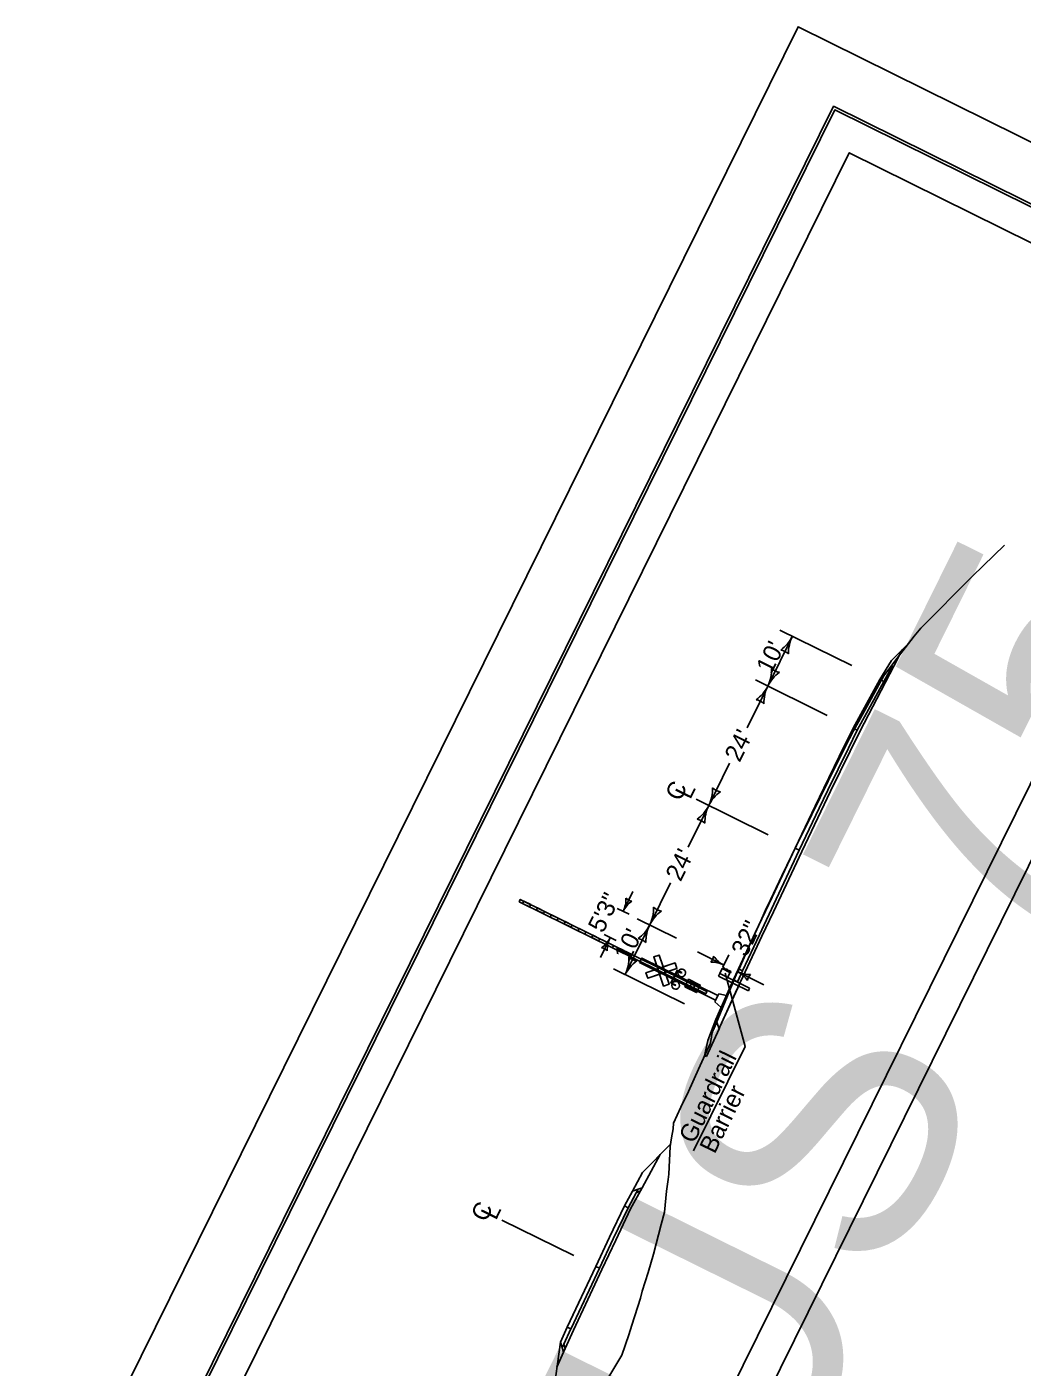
# Model space of a CAD drawing. Extents: x 14090526 to 14125274, y 8637242 to 8677144.
# Drawn here: x 14118796 to 14119513, y 8672010 to 8672975 of the extents above; entities that cross this region are included whole.
import ezdxf

# ---------------------------------------------------------------- set-up
doc = ezdxf.new("R2010")
doc.units = 0
for name, color, linetype in [('dsnCellElements', 7, 'Continuous'), ('dsnNonPlotable', 7, 'Continuous'), ('dsnShadingGranular', 7, 'Continuous'), ('dsnShadingPaved', 7, 'Continuous'), ('dsnStdLineWork', 7, 'Continuous'), ('dsnStgShadingPropPav', 7, 'Continuous'), ('dsnTextOverlapEven', 7, 'Continuous'), ('Level 1', 7, 'Continuous'), ('TC_PCCPavement', 7, 'Continuous'), ('TC_ShoulderEarthFill', 7, 'Continuous'), ('TC_ShoulderGranular', 7, 'Continuous'), ('TC_Subbase', 7, 'Continuous'), ('Terrain', 7, 'Continuous')]:
    doc.layers.add(name, color=color, linetype=linetype)

# ---------------------------------------------------------------- blocks, each defined once
blk = doc.blocks.new('LT')
at = {"layer": 'dsnCellElements'}
for centre, radius, start, end in [((-3.56, 0), 1.64, 342.2666, 17.7333), ((0, 4.25), 4.25, 241.9275, 270), ((0, -4.25), 4.25, 90, 118.0725)]:
    blk.add_arc(centre, radius, start, end, dxfattribs=at)

msp = doc.modelspace()

# ---------------------------------------------------------------- linework, layer by layer
at = {"layer": 'dsnNonPlotable'}
for points in [[(14118795.85, 8671851.12), (14119351.63, 8672975.23), (14120075.94, 8672617.11), (14119520.16, 8671493)], [(14118861.25, 8671870.1), (14119378.04, 8672915.32), (14120012.79, 8672601.49), (14119496.01, 8671556.26)]]:
    msp.add_lwpolyline(points, close=True, dxfattribs=at)
at = {"layer": 'dsnShadingGranular'}
for points in [[(14119294.62, 8672253.43), (14119292.31, 8672260.25), (14119304.91, 8672288.51), (14119307.9, 8672287.03), (14119309.61, 8672286.19), (14119295.27, 8672254.87)], [(14119226.42, 8672126), (14119232.2, 8672136.6), (14119236.39, 8672138.03), (14119234.89, 8672135.27), (14119234.89, 8672135.27), (14119229.11, 8672124.67)], [(14119181.56, 8672023.96), (14119180.29, 8672027.72), (14119185.2, 8672038.75), (14119187.88, 8672037.42), (14119182.75, 8672026.5), (14119182.75, 8672026.5)]]:
    msp.add_lwpolyline(points, close=True, dxfattribs=at)
at = {"layer": 'dsnShadingPaved'}
for points in [[(14119311.6, 8672295.34), (14119323.72, 8672321.14), (14119335.84, 8672346.95), (14119352.39, 8672382.18), (14119359.62, 8672397.31), (14119366.84, 8672412.45), (14119373.09, 8672425.47), (14119387.87, 8672455.61), (14119394.29, 8672468.54), (14119391.3, 8672470.02), (14119384.88, 8672457.08), (14119370.1, 8672426.95), (14119363.86, 8672413.93), (14119356.63, 8672398.79), (14119349.4, 8672383.65), (14119332.85, 8672348.43), (14119320.73, 8672322.61), (14119308.61, 8672296.81)], [(14119185.2, 8672038.75), (14119205.79, 8672082.38), (14119215.78, 8672103.47), (14119226.42, 8672126), (14119229.11, 8672124.67), (14119218.46, 8672102.14), (14119208.48, 8672081.06), (14119188.04, 8672037.74), (14119187.89, 8672037.42)]]:
    msp.add_lwpolyline(points, close=True, dxfattribs=at)
at = {"layer": 'dsnStdLineWork'}
for p, q in [((14119150.63, 8672345.1), (14119151.45, 8672346.76)), ((14119285.08, 8672278.62), (14119150.63, 8672345.1)), ((14119285.91, 8672280.28), (14119151.45, 8672346.76)), ((14119237.36, 8672301.18), (14119239.01, 8672304.5)), ((14119293.79, 8672277.41), (14119239.01, 8672304.5)), ((14119292.14, 8672274.09), (14119237.36, 8672301.18)), ((14119264.45, 8672295.69), (14119259.81, 8672286.31)), ((14119264.66, 8672295.07), (14119260.43, 8672286.52)), ((14119267.89, 8672293.99), (14119264.45, 8672295.69)), ((14119267.69, 8672293.57), (14119264.66, 8672295.07)), ((14119267.69, 8672293.57), (14119267.89, 8672293.99)), ((14119263.26, 8672284.61), (14119259.81, 8672286.31)), ((14119263.46, 8672285.02), (14119260.43, 8672286.52)), ((14119263.26, 8672284.61), (14119263.46, 8672285.02)), ((14119285.08, 8672278.62), (14119285.91, 8672280.28)), ((14119291.53, 8672272.85), (14119294.4, 8672278.66)), ((14119294.4, 8672278.66), (14119300, 8672277.44)), ((14119291.53, 8672272.85), (14119295.89, 8672269.14))]:
    msp.add_line(p, q, dxfattribs=at)
for points in [[(14119150.63, 8672345.1), (14119151.45, 8672346.76), (14119285.91, 8672280.28), (14119285.08, 8672278.62)], [(14119153.12, 8672343.87), (14119153.94, 8672345.53), (14119158.92, 8672343.06), (14119158.1, 8672341.4)], [(14119163.08, 8672338.94), (14119163.9, 8672340.6), (14119168.88, 8672338.14), (14119168.06, 8672336.48)], [(14119173.04, 8672334.02), (14119173.86, 8672335.68), (14119178.84, 8672333.21), (14119178.02, 8672331.55)], [(14119183, 8672329.09), (14119183.82, 8672330.75), (14119188.8, 8672328.29), (14119187.98, 8672326.63)], [(14119192.96, 8672324.17), (14119193.78, 8672325.83), (14119198.76, 8672323.37), (14119197.94, 8672321.71)], [(14119202.92, 8672319.24), (14119203.74, 8672320.9), (14119208.72, 8672318.44), (14119207.9, 8672316.78)], [(14119212.88, 8672314.32), (14119213.7, 8672315.98), (14119218.68, 8672313.52), (14119217.86, 8672311.86)], [(14119222.84, 8672309.39), (14119223.66, 8672311.05), (14119228.64, 8672308.59), (14119227.82, 8672306.93)], [(14119232.8, 8672304.47), (14119233.62, 8672306.13), (14119238.6, 8672303.67), (14119237.77, 8672302.01)], [(14119237.36, 8672301.18), (14119239.01, 8672304.5), (14119293.79, 8672277.41), (14119292.14, 8672274.09)], [(14119243.27, 8672289.92), (14119241.93, 8672293.86), (14119250.48, 8672296.76), (14119247.59, 8672305.31), (14119251.54, 8672306.64), (14119254.43, 8672298.09), (14119262.98, 8672300.99), (14119264.32, 8672297.04), (14119255.77, 8672294.15), (14119258.66, 8672285.59), (14119254.71, 8672284.26), (14119251.82, 8672292.81)], [(14119247.59, 8672305.31), (14119251.54, 8672306.64), (14119258.66, 8672285.59), (14119254.71, 8672284.26)], [(14119241.93, 8672293.86), (14119243.27, 8672289.92), (14119264.32, 8672297.04), (14119262.98, 8672300.99)], [(14119270.02, 8672283.69), (14119272.73, 8672289.17), (14119281.05, 8672285.06), (14119278.34, 8672279.57)]]:
    msp.add_lwpolyline(points, close=True, dxfattribs=at)
msp.add_circle((14119275.54, 8672284.37), 1.39, dxfattribs=at)
for centre in [(14119267.79, 8672293.78), (14119263.36, 8672284.81)]:
    msp.add_arc(centre, 2.78, 158.47136, 148.91098, dxfattribs=at)
at = {"layer": 'dsnStgShadingPropPav'}
for points in [[(14119391.3, 8672470.02), (14119410.47, 8672505.16), (14119413.45, 8672503.69), (14119407.69, 8672493.12), (14119394.29, 8672468.54)], [(14119307.9, 8672287.03), (14119304.91, 8672288.51), (14119308.61, 8672296.81), (14119311.6, 8672295.34)]]:
    msp.add_lwpolyline(points, close=True, dxfattribs=at)
at = {"layer": 'dsnTextOverlapEven'}
for p, q in [((14119329.75, 8672500.39), (14119347.51, 8672536.31)), ((14119390.28, 8672515.16), (14119338.54, 8672540.74)), ((14119372.55, 8672479.3), (14119320.81, 8672504.88)), ((14119314.91, 8672470.38), (14119329.75, 8672500.39)), ((14119287.23, 8672414.39), (14119302.25, 8672444.77)), ((14119330.01, 8672393.25), (14119278.27, 8672418.83)), ((14119272.4, 8672384.39), (14119287.23, 8672414.39)), ((14119225.52, 8672338.11), (14119232.61, 8672352.45)), ((14119244.71, 8672328.4), (14119259.73, 8672358.78)), ((14119229.79, 8672335.99), (14119221.25, 8672340.22)), ((14119263.96, 8672318.89), (14119235.75, 8672332.84)), ((14119220.48, 8672317.17), (14119211.94, 8672321.39)), ((14119226.99, 8672292.55), (14119244.71, 8672328.4)), ((14119209.12, 8672304.94), (14119216.21, 8672319.28)), ((14119298.19, 8672299.45), (14119279.03, 8672308.93)), ((14119297.42, 8672297.88), (14119301.8, 8672306.75)), ((14119269.76, 8672271.4), (14119218.71, 8672296.64)), ((14119295.16, 8672293.33), (14119294.28, 8672291.54)), ((14119295.16, 8672293.33), (14119296.94, 8672296.91)), ((14119295.16, 8672293.33), (14119316.68, 8672282.69)), ((14119296.94, 8672296.91), (14119302.91, 8672293.96)), ((14119300.84, 8672290.52), (14119302.61, 8672294.11)), ((14119306.98, 8672293.16), (14119311.36, 8672302.02)), ((14119326.95, 8672285.23), (14119307.75, 8672294.73)), ((14119294.28, 8672291.54), (14119315.79, 8672280.9)), ((14119316.68, 8672282.69), (14119315.79, 8672280.9)), ((14119189.99, 8672090.2), (14119138.25, 8672115.78))]:
    msp.add_line(p, q, dxfattribs=at)
for points in [[(14118892.07, 8671880.52), (14119388.46, 8672884.51), (14119674.02, 8672743.33), (14119177.62, 8671739.34)], [(14119200.03, 8671728.26), (14119696.43, 8672732.25), (14119981.98, 8672591.06), (14119485.59, 8671587.07)]]:
    msp.add_lwpolyline(points, close=True, dxfattribs=at)
msp.add_lwpolyline([(14119276.23, 8672165.58), (14119313.44, 8672240.83), (14119299.14, 8672293.54)], dxfattribs=at)
for centre, major_axis, ratio, start_param, end_param in [((14119297.86, 8672296.46), (-0.48, -0.971), 0.951924, 1.570796, 4.712389), ((14119299.92, 8672295.44), (-1.14, 0.56), 0.852459, 3.141593, 6.283185), ((14119301.99, 8672294.42), (-0.481, -0.973), 0.949899, 1.570796, 4.712389)]:
    msp.add_ellipse(centre, major_axis=major_axis, ratio=ratio, start_param=start_param, end_param=end_param, dxfattribs=at)
at = {"layer": 'Level 1'}
msp.add_lwpolyline([(14118858.58, 8671869.19), (14119377.13, 8672918), (14120015.47, 8672602.39), (14119496.92, 8671553.58)], close=True, dxfattribs=at)
at = {"layer": 'TC_PCCPavement'}
for p, q in [((14119410.47, 8672505.16), (14119413.45, 8672503.69)), ((14119391.3, 8672470.02), (14119394.29, 8672468.54)), ((14119349.4, 8672383.64), (14119352.38, 8672382.16)), ((14119308.61, 8672296.81), (14119311.6, 8672295.34)), ((14119305.04, 8672288.82), (14119304.91, 8672288.51)), ((14119305.04, 8672288.82), (14119308.03, 8672287.34)), ((14119308.03, 8672287.34), (14119307.9, 8672287.03)), ((14119226.42, 8672126), (14119229.11, 8672124.67)), ((14119205.79, 8672082.38), (14119208.48, 8672081.06)), ((14119185.2, 8672038.75), (14119185.35, 8672039.07)), ((14119185.2, 8672038.75), (14119187.89, 8672037.42)), ((14119187.89, 8672037.42), (14119188.04, 8672037.74))]:
    msp.add_line(p, q, dxfattribs=at)
for points in [[(14119305.04, 8672288.82), (14119308.61, 8672296.81), (14119320.73, 8672322.61), (14119332.85, 8672348.43), (14119349.4, 8672383.65), (14119356.63, 8672398.79), (14119363.86, 8672413.93), (14119370.1, 8672426.95), (14119384.88, 8672457.08), (14119391.3, 8672470.02), (14119404.7, 8672494.59), (14119410.47, 8672505.16)], [(14119308.03, 8672287.34), (14119311.6, 8672295.34), (14119323.72, 8672321.14), (14119335.84, 8672346.95), (14119352.39, 8672382.18), (14119359.62, 8672397.31), (14119366.84, 8672412.45), (14119373.09, 8672425.47), (14119387.87, 8672455.61), (14119394.29, 8672468.54), (14119407.69, 8672493.12), (14119413.45, 8672503.69)], [(14119185.35, 8672039.07), (14119205.79, 8672082.38), (14119215.78, 8672103.47), (14119226.42, 8672126)], [(14119188.04, 8672037.74), (14119208.48, 8672081.06), (14119218.46, 8672102.14), (14119229.11, 8672124.67)]]:
    msp.add_lwpolyline(points, dxfattribs=at)
at = {"layer": 'TC_ShoulderEarthFill'}
for p, q in [((14119420.51, 8672514.68), (14119426.7, 8672526.57)), ((14119294.62, 8672253.43), (14119285.5, 8672233.52)), ((14119285.5, 8672233.52), (14119284.25, 8672234.14)), ((14119239.19, 8672138.98), (14119252.27, 8672162.95)), ((14119177.81, 8672009.84), (14119182.65, 8672020.72))]:
    msp.add_line(p, q, dxfattribs=at)
at = {"layer": 'TC_ShoulderGranular'}
for q in [(14119304.91, 8672288.51), (14119294.62, 8672253.43)]:
    msp.add_line((14119292.31, 8672260.25), q, dxfattribs=at)
for points in [[(14119226.42, 8672126), (14119232.2, 8672136.6), (14119239.19, 8672138.98)], [(14119185.2, 8672038.75), (14119180.29, 8672027.72), (14119182.65, 8672020.72)]]:
    msp.add_lwpolyline(points, dxfattribs=at)
at = {"layer": 'TC_Subbase'}
for p, q in [((14119238.03, 8672136.85), (14119239.19, 8672138.98)), ((14119182.65, 8672020.72), (14119183.81, 8672023.34))]:
    msp.add_line(p, q, dxfattribs=at)
for points in [[(14119294.62, 8672253.43), (14119295.27, 8672254.87), (14119306.62, 8672279.66), (14119313.39, 8672294.45), (14119325.51, 8672320.25), (14119333.8, 8672337.9), (14119354.21, 8672381.26), (14119374.89, 8672424.59), (14119396.08, 8672467.65), (14119414.53, 8672503.16), (14119420.51, 8672514.68)], [(14119413.45, 8672503.69), (14119419.2, 8672514.23), (14119420.51, 8672514.68)], [(14119183.81, 8672023.34), (14119189.68, 8672036.53), (14119200.05, 8672058.51), (14119210.27, 8672080.17), (14119220.26, 8672101.25), (14119230.9, 8672123.79), (14119238.03, 8672136.85)], [(14119229.11, 8672124.67), (14119234.89, 8672135.27), (14119238.03, 8672136.85)], [(14119183.81, 8672023.34), (14119182.75, 8672026.5), (14119187.88, 8672037.42)]]:
    msp.add_lwpolyline(points, dxfattribs=at)
at = {"layer": 'Terrain'}
msp.add_line((14119180.29, 8672027.72), (14119162.95, 8671903.11), dxfattribs=at)
for points in [[(14119213.9, 8672000.57), (14119224.61, 8672018.56), (14119229.57, 8672033.1), (14119231.83, 8672040.12), (14119238.14, 8672059.54), (14119239.3, 8672064.68), (14119243.46, 8672078), (14119247.49, 8672091.31), (14119252.89, 8672112.5), (14119255.32, 8672121.58), (14119256.84, 8672136.62), (14119257.95, 8672144.95), (14119258.45, 8672148.81), (14119259.34, 8672168.84), (14119260.48, 8672175.11), (14119261.63, 8672181.39), (14119261.91, 8672185.65), (14119267.23, 8672197.01), (14119272.56, 8672208.38), (14119279.8, 8672224.34), (14119287.04, 8672240.3), (14119288.37, 8672242.45), (14119289.2, 8672247.6), (14119289.36, 8672249.85), (14119289.9, 8672250.79), (14119290.02, 8672251.47), (14119290.61, 8672252.83), (14119299.04, 8672273.2), (14119307.47, 8672293.57), (14119308.19, 8672294.68), (14119316.44, 8672313.01), (14119324.68, 8672331.34), (14119327.93, 8672338.49), (14119331.64, 8672346.33), (14119339.91, 8672363.64), (14119350.47, 8672385.62), (14119361.41, 8672407.93), (14119379.38, 8672444.14), (14119388.72, 8672462.72), (14119391.58, 8672468.18), (14119401.42, 8672486.02), (14119411.25, 8672503.85), (14119412.8, 8672506.78), (14119413.4, 8672507.76), (14119420.55, 8672517.48), (14119435.16, 8672536.36), (14119440, 8672542.11), (14119477.34, 8672579.51), (14119500.29, 8672601.84)], [(14119410.47, 8672505.16), (14119418.99, 8672518.8), (14119426.7, 8672526.57), (14119430.76, 8672530.68)], [(14119284.25, 8672234.14), (14119286.66, 8672245.2), (14119292.31, 8672260.25)], [(14119232.2, 8672136.6), (14119239.58, 8672150.12), (14119259.62, 8672170.38)]]:
    msp.add_lwpolyline(points, dxfattribs=at)

# ---------------------------------------------------------------- block references
at = {"layer": 'dsnTextOverlapEven'}
for p, xscale, yscale, rotation in [((14119347.47, 8672536.24), 6.308076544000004, 6.308076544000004, 63.69110745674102), ((14119329.75, 8672500.39), 6.308076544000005, 6.308076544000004, -116.30889254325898), ((14119329.75, 8672500.39), 6.308076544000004, 6.308076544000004, 63.69110745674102), ((14119287.23, 8672414.39), 6.308076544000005, 6.308076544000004, -116.30889254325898), ((14119287.23, 8672414.39), 6.308076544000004, 6.308076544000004, 63.69110745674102), ((14119225.52, 8672338.11), 4.731057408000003, 4.731057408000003, -116.30889254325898), ((14119244.71, 8672328.4), 6.308076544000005, 6.308076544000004, -116.30889254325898), ((14119244.71, 8672328.4), 6.308076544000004, 6.308076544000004, 63.69110745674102), ((14119216.21, 8672319.28), 4.7310574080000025, 4.7310574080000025, 63.69110745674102), ((14119226.99, 8672292.55), 6.308076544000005, 6.308076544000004, -116.30889254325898), ((14119298.19, 8672299.45), 4.7310574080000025, -4.731057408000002, -26.30877033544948), ((14119307.75, 8672294.73), 4.7310574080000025, -4.731057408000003, 153.69122966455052)]:
    msp.add_blockref('LT', p, dxfattribs=dict(at, xscale=xscale, yscale=yscale, rotation=rotation))

# ---------------------------------------------------------------- texts
for s, rotation, p in [("10'", 63.69111, (14119332.26, 8672508.44)), ("24'", 63.69111, (14119309.46, 8672444.91)), ('C', 63.69111, (14119266.73, 8672416.75)), ('L', 63.69111, (14119273.92, 8672418.17)), ("24'", 63.69111, (14119266.94, 8672358.92)), ('5\'3"', 63.69111, (14119211.07, 8672321.84)), ('32"', 63.69123, (14119314.27, 8672304.66)), ("10'", 63.69111, (14119229.9, 8672301.41)), ('Guardrail', 63.69123, (14119276.54, 8672170.23)), ('Barrier', 63.69123, (14119291.46, 8672162.86)), ('C', 63.69111, (14119126.71, 8672113.7)), ('L', 63.69111, (14119133.9, 8672115.12))]:
    msp.add_text(s, height=12.8, rotation=rotation, dxfattribs=at).set_placement(p)
at = {"layer": 'TC_PCCPavement'}
msp.add_text('US 75', height=192, rotation=63.69117, dxfattribs=at).set_placement((14119331.71, 8671898.58))

doc.saveas('drawing.dxf')
